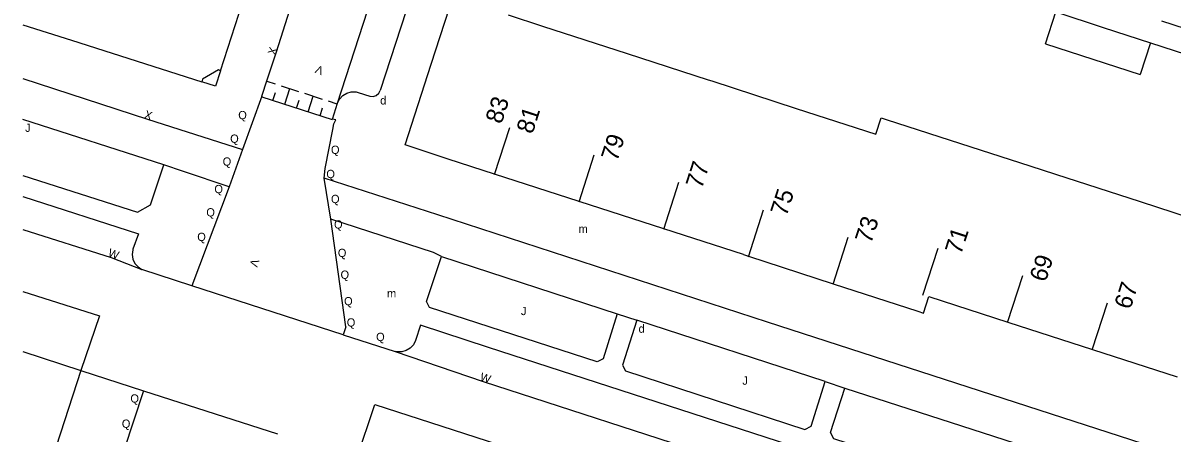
# Model space of a CAD drawing. Extents: x 134999 to 136502, y 457398 to 459002.
# Drawn here: x 135000 to 135069.7, y 457953.9 to 457978.8 of the extents above; entities that cross this region are included whole.
import ezdxf

# ---------------------------------------------------------------- set-up
doc = ezdxf.new("R2010")
doc.units = 0
for name, color, linetype in [('RI_DGTB_15', 7, 'Continuous'), ('RI_DGTB_2', 7, 'Continuous'), ('RI_DGTB_29', 7, 'Continuous'), ('RI_DGTB_30', 7, 'Continuous'), ('RI_DGTB_31', 7, 'Continuous'), ('RI_DGTB_35', 7, 'Continuous'), ('RI_DGTB_36', 7, 'Continuous'), ('RI_DGTB_4', 7, 'Continuous'), ('RI_DGTB_43', 7, 'Continuous'), ('RI_DGTB_53', 7, 'Continuous'), ('RI_DGTB_6', 7, 'Continuous')]:
    doc.layers.add(name, color=color, linetype=linetype)

msp = doc.modelspace()

# ---------------------------------------------------------------- linework, layer by layer
at = {"layer": 'RI_DGTB_15'}
for p, q in [((135028.615, 457969.615), (135029.54, 457972.47)), ((135033.753, 457967.952), (135034.678, 457970.807)), ((135038.89, 457966.289), (135039.815, 457969.144)), ((135044.028, 457964.625), (135044.953, 457967.48)), ((135049.165, 457962.962), (135050.09, 457965.817)), ((135054.626, 457962.298), (135055.551, 457965.153)), ((135059.763, 457960.634), (135060.688, 457963.489)), ((135064.901, 457958.971), (135065.826, 457961.826))]:
    msp.add_line(p, q, dxfattribs=at)
at = {"layer": 'RI_DGTB_2'}
for points in [[(135024.779, 457976.295), (135027.522, 457984.776)], [(135029.444, 457979.291), (135031.528, 457978.616)], [(135031.528, 457978.616), (135036.666, 457976.952)], [(135036.666, 457976.952), (135041.579, 457975.36)], [(135028.623, 457969.64), (135025.806, 457970.551), (135023.198, 457971.412), (135024.779, 457976.295)], [(135041.579, 457975.36), (135041.803, 457975.287)], [(135041.803, 457975.287), (135046.939, 457973.62)], [(135046.939, 457973.62), (135051.763, 457972.054), (135052.096, 457973.053), (135052.399, 457972.955)], [(135052.399, 457972.955), (135057.538, 457971.294)], [(135057.538, 457971.294), (135061.116, 457970.137), (135062.675, 457969.632)], [(135033.761, 457967.978), (135028.623, 457969.64)], [(135062.675, 457969.632), (135067.813, 457967.969)], [(135038.899, 457966.316), (135033.761, 457967.978)], [(135067.813, 457967.969), (135072.951, 457966.306)], [(135043.726, 457964.754), (135038.899, 457966.316)], [(135043.726, 457964.754), (135044.037, 457964.653)], [(135044.037, 457964.653), (135049.173, 457962.989)], [(135049.173, 457962.989), (135054.311, 457961.324)], [(135054.311, 457961.324), (135054.664, 457961.21), (135054.987, 457962.212), (135059.772, 457960.663)], [(135059.772, 457960.663), (135064.91, 457958.999)], [(135064.91, 457958.999), (135070.047, 457957.336)]]:
    msp.add_lwpolyline(points, dxfattribs=at)
at = {"layer": 'RI_DGTB_31'}
for p, q in [((135014.804, 457975.279), (135015.305, 457975.116)), ((135015.662, 457975), (135016.732, 457974.653)), ((135015.888, 457973.876), (135016.197, 457974.827)), ((135014.49, 457974.33), (135018.765, 457972.941)), ((135015.174, 457974.107), (135015.329, 457974.583)), ((135016.601, 457973.644), (135016.756, 457974.119)), ((135017.088, 457974.537), (135018.158, 457974.19)), ((135017.314, 457973.412), (135017.623, 457974.363)), ((135018.028, 457973.181), (135018.182, 457973.656)), ((135018.515, 457974.074), (135019.041, 457973.903))]:
    msp.add_line(p, q, dxfattribs=at)
at = {"layer": 'RI_DGTB_4'}
for p, q in [((135000, 457978.691), (135002.946, 457977.752)), ((135002.946, 457977.752), (135010.854, 457975.234))]:
    msp.add_line(p, q, dxfattribs=at)
for points in [[(135011.991, 457975.903), (135014.224, 457982.799), (135014.842, 457984.607)], [(135011.991, 457975.903), (135011.863, 457975.958), (135010.904, 457975.405), (135010.854, 457975.234)], [(135011.991, 457975.903), (135011.692, 457974.968), (135010.854, 457975.234)]]:
    msp.add_lwpolyline(points, dxfattribs=at)
at = {"layer": 'RI_DGTB_53'}
for p, q in [((135019.09, 457973.935), (135022.852, 457985.562)), ((135068.436, 457977.605), (135072.95, 457976.142)), ((135014.499, 457974.357), (135013.325, 457971.12)), ((135020.353, 457974.593), (135021.06, 457974.371)), ((135018.786, 457972.979), (135019.09, 457973.935)), ((135008.558, 457970.2), (135000, 457972.958)), ((135013.325, 457971.12), (135012.506, 457968.861)), ((135012.506, 457968.861), (135010.249, 457962.871)), ((135019.587, 457960.381), (135018.684, 457966.898)), ((135010.249, 457962.871), (135007.223, 457963.85)), ((135019.429, 457959.889), (135010.249, 457962.871)), ((135036.066, 457961.164), (135037.256, 457960.771)), ((135019.587, 457960.381), (135019.429, 457959.889)), ((135019.429, 457959.889), (135022.582, 457958.876)), ((135000, 457958.878), (135003.52, 457957.72)), ((135022.582, 457958.876), (135027.933, 457957.055)), ((135003.52, 457957.72), (135000.41, 457948.2)), ((135003.52, 457957.72), (135007.31, 457956.5)), ((135027.933, 457957.055), (135044.91, 457951.569)), ((135048.698, 457957.063), (135049.887, 457956.661)), ((135007.31, 457956.5), (135015.45, 457953.89))]:
    msp.add_line(p, q, dxfattribs=at)
for points in [[(135032.177, 458007.082), (135028.971, 457997.216), (135024.812, 457984.329), (135021.684, 457974.705)], [(135014.826, 457975.346), (135015.39, 457977.05), (135017.7, 457984.34), (135019.953, 457991.335)], [(135000, 457975.427), (135007.56, 457972.97), (135013.325, 457971.12)], [(135014.499, 457974.357), (135014.826, 457975.346)], [(135019.09, 457973.935), (135019.217, 457974.19), (135019.409, 457974.401), (135019.652, 457974.55), (135019.927, 457974.626), (135020.213, 457974.624), (135020.353, 457974.593)], [(135021.06, 457974.371), (135021.253, 457974.353), (135021.443, 457974.412), (135021.596, 457974.54), (135021.684, 457974.705)], [(135018.273, 457969.393), (135018.335, 457969.974), (135018.807, 457972.352), (135018.875, 457972.681), (135018.979, 457972.927), (135018.786, 457972.979)], [(135000, 457969.554), (135006.96, 457967.32), (135007.75, 457967.78), (135008.558, 457970.2)], [(135012.506, 457968.861), (135009.75, 457969.79), (135008.558, 457970.2)], [(135018.684, 457966.898), (135018.273, 457969.393)], [(135113.906, 457938.397), (135109.313, 457939.915), (135088.067, 457946.781), (135063.106, 457954.862), (135045.186, 457960.666), (135025.173, 457967.169), (135018.273, 457969.393)], [(135000, 457968.282), (135007.01, 457966.02), (135006.67, 457965.08), (135006.663, 457965.054), (135006.628, 457964.768), (135006.673, 457964.485), (135006.794, 457964.224), (135006.983, 457964.007), (135007.223, 457963.85)], [(135025.41, 457964.634), (135024.917, 457964.891), (135018.684, 457966.898)], [(135000, 457966.278), (135005.36, 457964.58), (135007.223, 457963.85)], [(135036.066, 457961.164), (135035.208, 457958.43), (135034.849, 457958.251), (135024.681, 457961.538), (135024.494, 457961.914), (135025.41, 457964.634)], [(135025.41, 457964.634), (135036.066, 457961.164)], [(135000, 457962.508), (135004.638, 457961.04), (135003.52, 457957.72)], [(135105.897, 457933.968), (135098.997, 457936.223), (135086.131, 457940.392), (135061.187, 457948.44), (135045.052, 457953.673), (135028.246, 457959.12), (135024.121, 457960.467), (135023.824, 457959.553)], [(135037.256, 457960.771), (135036.38, 457958.053), (135036.578, 457957.696), (135047.459, 457954.148)], [(135048.698, 457957.063), (135037.256, 457960.771)], [(135023.824, 457959.553), (135023.697, 457959.292), (135023.506, 457959.08), (135023.264, 457958.929), (135022.989, 457958.85), (135022.704, 457958.851), (135022.582, 457958.876)], [(135047.459, 457954.148), (135047.834, 457954.343), (135048.698, 457957.063)], [(135061.481, 457952.918), (135060.621, 457950.203), (135060.241, 457950.009), (135049.207, 457953.584), (135049.019, 457953.957), (135049.887, 457956.661)], [(135049.887, 457956.661), (135061.481, 457952.918)], [(135007.31, 457956.5), (135004.93, 457949.25), (135001.86, 457947.75), (135000.41, 457948.2)], [(135020.246, 457952.339), (135021.351, 457955.656), (135056.642, 457944.268), (135105.852, 457928.376), (135112.993, 457925.633), (135117.753, 457923.769), (135126.188, 457919.369), (135133.662, 457914.816)]]:
    msp.add_lwpolyline(points, dxfattribs=at)
at = {"layer": 'RI_DGTB_6'}
for p, q in [((135062.069, 457977.54), (135062.697, 457979.471)), ((135068.436, 457977.605), (135067.808, 457975.674))]:
    msp.add_line(p, q, dxfattribs=at)
for points in [[(135062.697, 457979.471), (135065.566, 457978.538)], [(135065.566, 457978.538), (135068.436, 457977.605)], [(135072, 457977.98), (135069.129, 457978.912)], [(135062.069, 457977.54), (135064.939, 457976.607)], [(135064.939, 457976.607), (135067.808, 457975.674)]]:
    msp.add_lwpolyline(points, dxfattribs=at)

# ---------------------------------------------------------------- texts
at = {"layer": 'RI_DGTB_29'}
for p in [(135021.68, 457973.858), (135037.365, 457960.014)]:
    msp.add_text('d', height=0.5, dxfattribs=at).set_placement(p)
at = {"layer": 'RI_DGTB_30'}
for s, rotation, p in [('X', 71.60559, (135015.311, 457976.813)), ('V', 157.86337, (135018.292, 457976.093)), ('X', 342.10752, (135007.322, 457973.047)), ('X', 342.10752, (135007.322, 457973.047)), ('X', 342.10752, (135007.322, 457973.047)), ('W', 340.50896, (135005.124, 457964.663)), ('W', 340.50896, (135005.124, 457964.663)), ('W', 340.50896, (135005.124, 457964.663)), ('V', 252.75777, (135013.875, 457964.534)), ('V', 252.75777, (135013.875, 457964.534)), ('V', 252.75777, (135013.875, 457964.534)), ('W', 341.70679, (135027.696, 457957.133))]:
    msp.add_text(s, height=0.5, rotation=rotation, dxfattribs=at).set_placement(p)
at = {"layer": 'RI_DGTB_31'}
for s, p in [('Q', (135013.066, 457972.966)), ('J', (135000.13, 457972.2)), ('J', (135000.13, 457972.2)), ('J', (135000.13, 457972.2)), ('Q', (135012.576, 457971.536)), ('Q', (135012.12, 457970.15)), ('Q', (135011.617, 457968.48)), ('Q', (135011.128, 457967.069)), ('Q', (135010.579, 457965.58)), ('Q', (135006.52, 457955.78)), ('Q', (135006.52, 457955.78)), ('Q', (135006.52, 457955.78)), ('Q', (135006, 457954.25)), ('Q', (135006, 457954.25)), ('Q', (135006, 457954.25))]:
    msp.add_text(s, height=0.5, rotation=359.99965, dxfattribs=at).set_placement(p)
for s, p in [('Q', (135018.694, 457970.863)), ('Q', (135018.412, 457969.395)), ('Q', (135018.695, 457967.879)), ('Q', (135018.879, 457966.337)), ('Q', (135019.111, 457964.609)), ('Q', (135019.275, 457963.286)), ('Q', (135019.49, 457961.682)), ('J', (135030.224, 457961.085)), ('Q', (135019.653, 457960.391)), ('Q', (135021.435, 457959.514)), ('J', (135043.662, 457956.863))]:
    msp.add_text(s, height=0.5, dxfattribs=at).set_placement(p)
at = {"layer": 'RI_DGTB_35'}
msp.add_text('83', height=1.054, rotation=72.06, dxfattribs=at).set_placement((135029.043, 457972.632))
at = {"layer": 'RI_DGTB_36'}
for s, p in [('81', (135030.923, 457972.023)), ('79', (135036.061, 457970.36)), ('77', (135041.198, 457968.697)), ('75', (135046.336, 457967.033)), ('73', (135051.473, 457965.37)), ('71', (135056.934, 457964.706)), ('69', (135062.071, 457963.042)), ('67', (135067.209, 457961.379))]:
    msp.add_text(s, height=1.054, rotation=72.06, dxfattribs=at).set_placement(p)
at = {"layer": 'RI_DGTB_43'}
for p in [(135033.724, 457966.064), (135022.097, 457962.156)]:
    msp.add_text('m', height=0.5, dxfattribs=at).set_placement(p)

doc.saveas('drawing.dxf')
